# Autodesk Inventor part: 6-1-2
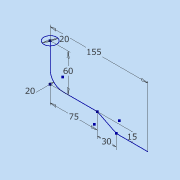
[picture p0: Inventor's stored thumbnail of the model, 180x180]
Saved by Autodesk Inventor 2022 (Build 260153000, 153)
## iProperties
Created: 2021-07
Part Number: 6-1-2
Material: 一般
Document SubType Name: Modeling
Designer: DesignLab
Density: 1 g/cm^3
Appearance: 既定
Author: DesignLab
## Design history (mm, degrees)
sketch "スケッチ1"
  geometry: C1 r 10 at (0, 0); 1 further point
  constraints: 1 centre point, 1 coincident
  dimensions: "d0" = 20 diameter of C1
sketch "スケッチ2"
  geometry: L1 (0, 0)-(0, -40); L2 (-20, -60)-(-70.279, -60); L3 (-79.223, -62.111)-(-100.777, -72.889); L4 (-109.721, -75)-(-155, -75); A1 r 20 centre (-20, -40) between (-20, -60) and (0, -40); A2 r 20 centre (-70.279, -80) between (-70.279, -60) and (-79.223, -62.111); A3 r 20 centre (-109.721, -55) between (-109.721, -75) and (-100.777, -72.889); 3 further points
  constraints: 8 end point, 6 point on circle, 6 point on line, 6 tangent, 3 centre point, 2 equal radius, 1 parallel, 1 perpendicular, 1 vertical
  dimensions: "d1" = 60 distance of L1.start point (0, -60); "d2" = 75 distance of point (0, -60) point (-75, -60); "d3" = 30 horizontal distance of point (-105, -75) point (-75, -60); "d4" = 15 distance between parallel lines of L4 L2; "d5" = 155 distance from line of L4.end L1; "d6" = 20 radius of A1
